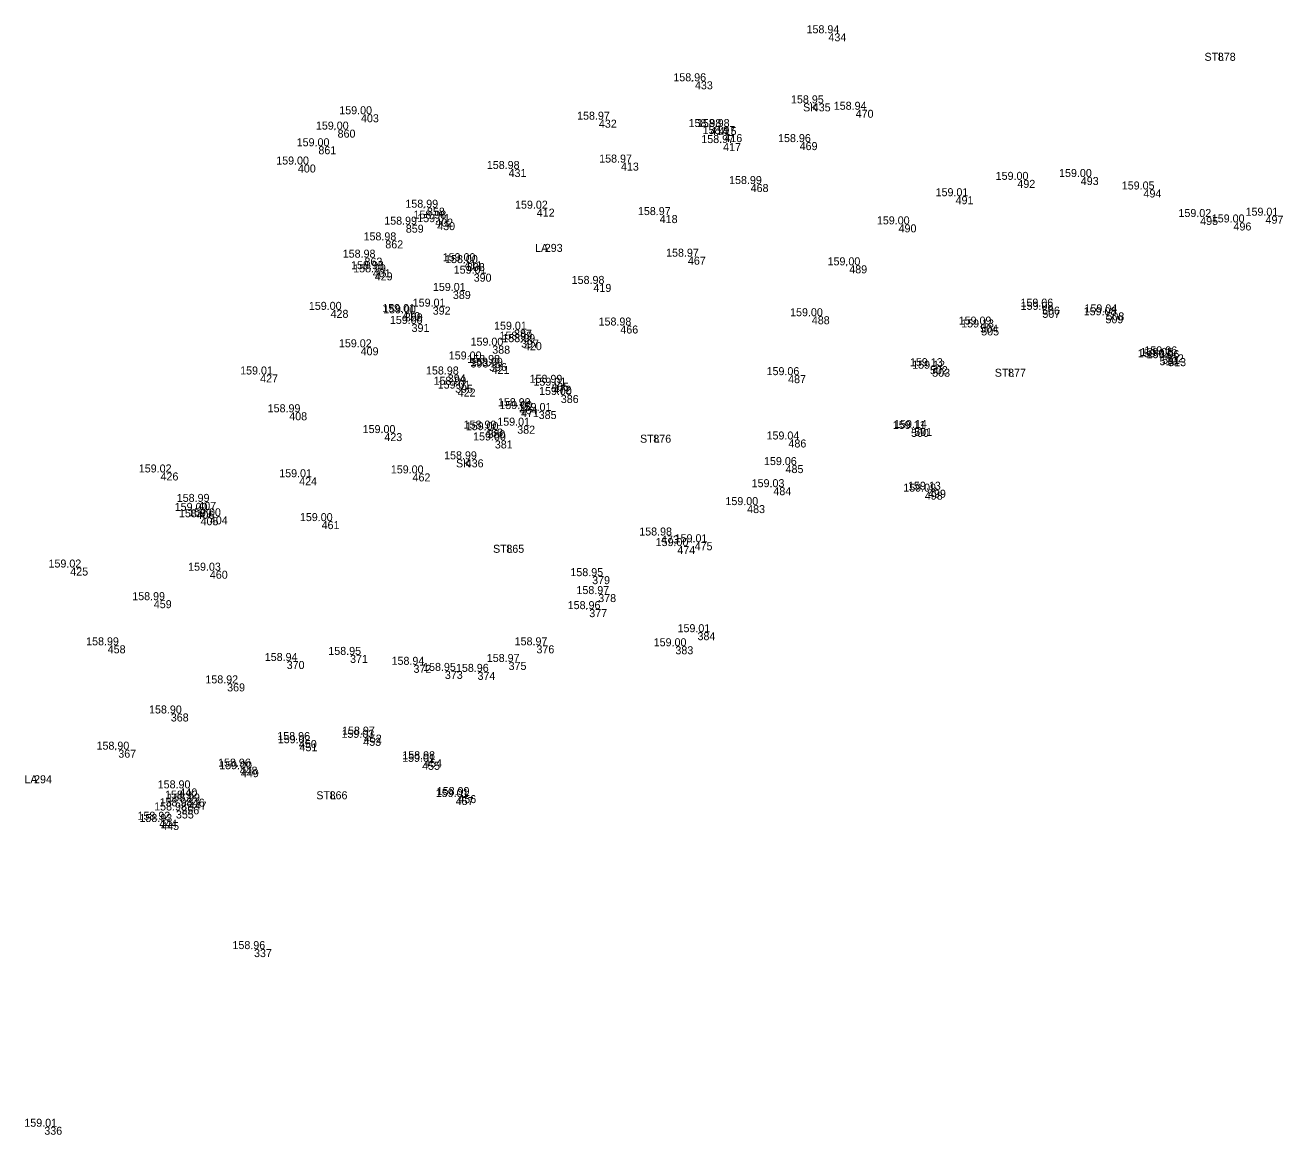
# Model space of a CAD drawing. Extents: x -583198 to -582878, y -1211024 to -1210637.
# Drawn here: x -583103.32 to -583064.04, y -1210915.85 to -1210881.19 of the extents above; entities that cross this region are included whole.
import ezdxf

# ---------------------------------------------------------------- set-up
doc = ezdxf.new("R2010")
doc.units = 0
for name, color, linetype in [('1   Kódy', 7, 'Continuous'), ('4   Body podrobné', 7, 'Continuous'), ('5   Body podrobné - čísla', 7, 'Continuous'), ('6   Body podrobné - výšky', 7, 'Continuous')]:
    doc.layers.add(name, color=color, linetype=linetype)

msp = doc.modelspace()

# ---------------------------------------------------------------- linework, layer by layer
at = {"layer": '4   Body podrobné'}
for p, q in [((-583078.32, -1210881.44), (-583078.319, -1210881.44)), ((-583066.16, -1210882.05), (-583066.159, -1210882.05)), ((-583082.49, -1210882.94), (-583082.489, -1210882.94)), ((-583078.81, -1210883.63), (-583078.809, -1210883.63)), ((-583077.47, -1210883.83), (-583077.469, -1210883.83)), ((-583092.92, -1210883.97), (-583092.919, -1210883.97)), ((-583085.49, -1210884.14), (-583085.489, -1210884.14)), ((-583093.65, -1210884.45), (-583093.649, -1210884.45)), ((-583082.01, -1210884.37), (-583082.009, -1210884.37)), ((-583081.75, -1210884.37), (-583081.749, -1210884.37)), ((-583081.57, -1210884.59), (-583081.569, -1210884.59)), ((-583094.25, -1210884.97), (-583094.249, -1210884.97)), ((-583081.61, -1210884.87), (-583081.609, -1210884.87)), ((-583079.22, -1210884.84), (-583079.219, -1210884.84)), ((-583084.8, -1210885.48), (-583084.799, -1210885.48)), ((-583094.89, -1210885.54), (-583094.889, -1210885.54)), ((-583088.31, -1210885.68), (-583088.309, -1210885.68)), ((-583080.75, -1210886.15), (-583080.749, -1210886.15)), ((-583072.42, -1210886.02), (-583072.419, -1210886.02)), ((-583070.44, -1210885.93), (-583070.439, -1210885.93)), ((-583068.48, -1210886.32), (-583068.479, -1210886.32)), ((-583074.35, -1210886.53), (-583074.349, -1210886.53)), ((-583090.86, -1210886.89), (-583090.859, -1210886.89)), ((-583087.43, -1210886.92), (-583087.429, -1210886.92)), ((-583091.52, -1210887.42), (-583091.519, -1210887.42)), ((-583090.6, -1210887.23), (-583090.599, -1210887.23)), ((-583090.54, -1210887.34), (-583090.539, -1210887.34)), ((-583083.59, -1210887.12), (-583083.589, -1210887.12)), ((-583076.13, -1210887.41), (-583076.129, -1210887.41)), ((-583066.71, -1210887.18), (-583066.709, -1210887.18)), ((-583065.67, -1210887.35), (-583065.669, -1210887.35)), ((-583064.67, -1210887.14), (-583064.669, -1210887.14)), ((-583092.16, -1210887.91), (-583092.159, -1210887.91)), ((-583087.18, -1210888.02), (-583087.179, -1210888.02)), ((-583092.81, -1210888.45), (-583092.809, -1210888.45)), ((-583089.69, -1210888.56), (-583089.689, -1210888.56)), ((-583089.61, -1210888.62), (-583089.609, -1210888.62)), ((-583082.71, -1210888.42), (-583082.709, -1210888.42)), ((-583092.55, -1210888.81), (-583092.549, -1210888.81)), ((-583092.49, -1210888.91), (-583092.489, -1210888.91)), ((-583089.4, -1210888.95), (-583089.399, -1210888.95)), ((-583077.67, -1210888.69), (-583077.669, -1210888.69)), ((-583085.66, -1210889.27), (-583085.659, -1210889.27)), ((-583090.05, -1210889.49), (-583090.049, -1210889.49)), ((-583093.87, -1210890.08), (-583093.869, -1210890.08)), ((-583091.63, -1210890.15), (-583091.629, -1210890.15)), ((-583091.55, -1210890.19), (-583091.549, -1210890.19)), ((-583090.68, -1210889.98), (-583090.679, -1210889.98)), ((-583071.65, -1210889.98), (-583071.649, -1210889.98)), ((-583071.64, -1210890.08), (-583071.639, -1210890.08)), ((-583069.64, -1210890.16), (-583069.639, -1210890.16)), ((-583091.34, -1210890.52), (-583091.339, -1210890.52)), ((-583084.82, -1210890.57), (-583084.819, -1210890.57)), ((-583078.84, -1210890.28), (-583078.839, -1210890.28)), ((-583073.58, -1210890.54), (-583073.579, -1210890.54)), ((-583073.55, -1210890.63), (-583073.549, -1210890.63)), ((-583069.67, -1210890.25), (-583069.669, -1210890.25)), ((-583088.14, -1210890.7), (-583088.139, -1210890.7)), ((-583087.92, -1210891.01), (-583087.919, -1210891.01)), ((-583092.93, -1210891.25), (-583092.929, -1210891.25)), ((-583088.82, -1210891.2), (-583088.819, -1210891.2)), ((-583087.83, -1210891.09), (-583087.829, -1210891.09)), ((-583089.5, -1210891.63), (-583089.499, -1210891.63)), ((-583088.92, -1210891.74), (-583088.919, -1210891.74)), ((-583067.98, -1210891.56), (-583067.979, -1210891.56)), ((-583067.9, -1210891.52), (-583067.899, -1210891.52)), ((-583067.78, -1210891.47), (-583067.779, -1210891.47)), ((-583067.71, -1210891.59), (-583067.709, -1210891.59)), ((-583096.07, -1210892.1), (-583096.069, -1210892.1)), ((-583090.21, -1210892.1), (-583090.209, -1210892.1)), ((-583088.84, -1210891.83), (-583088.839, -1210891.83)), ((-583079.58, -1210892.12), (-583079.579, -1210892.12)), ((-583075.15, -1210891.84), (-583075.149, -1210891.84)), ((-583075.08, -1210891.92), (-583075.079, -1210891.92)), ((-583072.71, -1210891.92), (-583072.709, -1210891.92)), ((-583089.98, -1210892.42), (-583089.979, -1210892.42)), ((-583089.9, -1210892.54), (-583089.899, -1210892.54)), ((-583086.98, -1210892.36), (-583086.979, -1210892.36)), ((-583086.91, -1210892.45), (-583086.909, -1210892.45)), ((-583086.68, -1210892.74), (-583086.679, -1210892.74)), ((-583095.16, -1210893.28), (-583095.159, -1210893.28)), ((-583087.97, -1210893.09), (-583087.969, -1210893.09)), ((-583087.92, -1210893.18), (-583087.919, -1210893.18)), ((-583087.37, -1210893.24), (-583087.369, -1210893.24)), ((-583088.04, -1210893.7), (-583088.039, -1210893.7)), ((-583075.64, -1210893.77), (-583075.639, -1210893.77)), ((-583092.19, -1210893.93), (-583092.189, -1210893.93)), ((-583089.04, -1210893.79), (-583089.039, -1210893.79)), ((-583088.97, -1210893.84), (-583088.969, -1210893.84)), ((-583088.74, -1210894.16), (-583088.739, -1210894.16)), ((-583083.79, -1210893.98), (-583083.789, -1210893.98)), ((-583079.57, -1210894.13), (-583079.569, -1210894.13)), ((-583075.74, -1210893.8), (-583075.739, -1210893.8)), ((-583089.65, -1210894.75), (-583089.649, -1210894.75)), ((-583079.66, -1210894.93), (-583079.659, -1210894.93)), ((-583099.18, -1210895.16), (-583099.179, -1210895.16)), ((-583094.85, -1210895.31), (-583094.849, -1210895.31)), ((-583091.31, -1210895.19), (-583091.309, -1210895.19)), ((-583080.04, -1210895.62), (-583080.039, -1210895.62)), ((-583075.21, -1210895.7), (-583075.209, -1210895.7)), ((-583098, -1210896.08), (-583097.999, -1210896.08)), ((-583075.31, -1210895.76), (-583075.309, -1210895.76)), ((-583098.06, -1210896.36), (-583098.059, -1210896.36)), ((-583097.64, -1210896.53), (-583097.639, -1210896.53)), ((-583080.86, -1210896.18), (-583080.859, -1210896.18)), ((-583097.93, -1210896.56), (-583097.929, -1210896.56)), ((-583094.15, -1210896.68), (-583094.149, -1210896.68)), ((-583083.55, -1210897.13), (-583083.549, -1210897.13)), ((-583088.38, -1210897.42), (-583088.379, -1210897.42)), ((-583083.04, -1210897.46), (-583083.039, -1210897.46)), ((-583082.5, -1210897.34), (-583082.499, -1210897.34)), ((-583102, -1210898.13), (-583101.999, -1210898.13)), ((-583097.64, -1210898.23), (-583097.639, -1210898.23)), ((-583085.7, -1210898.4), (-583085.699, -1210898.4)), ((-583099.39, -1210899.15), (-583099.389, -1210899.15)), ((-583085.51, -1210898.96), (-583085.509, -1210898.96)), ((-583085.79, -1210899.43), (-583085.789, -1210899.43)), ((-583082.41, -1210900.15), (-583082.409, -1210900.15)), ((-583100.83, -1210900.56), (-583100.829, -1210900.56)), ((-583087.44, -1210900.56), (-583087.439, -1210900.56)), ((-583083.1, -1210900.59), (-583083.099, -1210900.59)), ((-583095.24, -1210901.05), (-583095.239, -1210901.05)), ((-583093.26, -1210900.86), (-583093.259, -1210900.86)), ((-583091.28, -1210901.17), (-583091.279, -1210901.17)), ((-583088.31, -1210901.08), (-583088.309, -1210901.08)), ((-583090.3, -1210901.36), (-583090.299, -1210901.36)), ((-583089.28, -1210901.39), (-583089.279, -1210901.39)), ((-583097.1, -1210901.75), (-583097.099, -1210901.75)), ((-583098.86, -1210902.69), (-583098.859, -1210902.69)), ((-583094.86, -1210903.52), (-583094.859, -1210903.52)), ((-583092.85, -1210903.45), (-583092.849, -1210903.45)), ((-583092.83, -1210903.35), (-583092.829, -1210903.35)), ((-583100.5, -1210903.82), (-583100.499, -1210903.82)), ((-583094.84, -1210903.62), (-583094.839, -1210903.62)), ((-583096.71, -1210904.35), (-583096.709, -1210904.35)), ((-583091.01, -1210904.2), (-583091.009, -1210904.2)), ((-583090.95, -1210904.12), (-583090.949, -1210904.12)), ((-583103.13, -1210904.62), (-583103.129, -1210904.62)), ((-583096.67, -1210904.43), (-583096.669, -1210904.43)), ((-583098.59, -1210905.03), (-583098.589, -1210905.03)), ((-583093.9, -1210905.12), (-583093.899, -1210905.12)), ((-583098.36, -1210905.35), (-583098.359, -1210905.35)), ((-583098.3, -1210905.44), (-583098.299, -1210905.44)), ((-583089.96, -1210905.3), (-583089.959, -1210905.3)), ((-583089.88, -1210905.24), (-583089.879, -1210905.24)), ((-583098.7, -1210905.72), (-583098.699, -1210905.72)), ((-583098.53, -1210905.59), (-583098.529, -1210905.59)), ((-583099.22, -1210906.01), (-583099.219, -1210906.01)), ((-583099.16, -1210906.08), (-583099.159, -1210906.08)), ((-583096.26, -1210910.05), (-583096.259, -1210910.05)), ((-583102.81, -1210915.6), (-583102.809, -1210915.6))]:
    msp.add_line(p, q, dxfattribs=at)

# ---------------------------------------------------------------- texts
at = {"layer": '1   Kódy'}
for s, p in [('STL', (-583066.482, -1210882.3)), ('SK', (-583079.019, -1210883.88)), ('LA', (-583087.39, -1210888.27)), ('STL', (-583073.032, -1210892.17)), ('STL', (-583084.112, -1210894.23)), ('SK', (-583089.859, -1210895)), ('STL', (-583088.702, -1210897.67)), ('LA', (-583103.34, -1210904.87)), ('STL', (-583094.222, -1210905.37))]:
    msp.add_text(s, height=0.25, dxfattribs=at).set_placement(p)
at = {"layer": '5   Body podrobné - čísla'}
for s, p in [(' 434', (-583078.32, -1210881.69)), (' 878', (-583066.16, -1210882.3)), (' 433', (-583082.49, -1210883.19)), (' 435', (-583078.81, -1210883.88)), (' 470', (-583077.47, -1210884.08)), (' 403', (-583092.92, -1210884.22)), (' 432', (-583085.49, -1210884.39)), (' 860', (-583093.65, -1210884.7)), (' 414', (-583082.01, -1210884.62)), (' 415', (-583081.75, -1210884.62)), (' 416', (-583081.57, -1210884.84)), (' 861', (-583094.25, -1210885.22)), (' 417', (-583081.61, -1210885.12)), (' 469', (-583079.22, -1210885.09)), (' 413', (-583084.8, -1210885.73)), (' 400', (-583094.89, -1210885.79)), (' 431', (-583088.31, -1210885.93)), (' 493', (-583070.44, -1210886.18)), (' 468', (-583080.75, -1210886.4)), (' 492', (-583072.42, -1210886.27)), (' 494', (-583068.48, -1210886.57)), (' 491', (-583074.35, -1210886.78)), (' 858', (-583090.86, -1210887.14)), (' 412', (-583087.43, -1210887.17)), (' 859', (-583091.52, -1210887.67)), (' 402', (-583090.6, -1210887.48)), (' 430', (-583090.54, -1210887.59)), (' 418', (-583083.59, -1210887.37)), (' 490', (-583076.13, -1210887.66)), (' 495', (-583066.71, -1210887.43)), (' 496', (-583065.67, -1210887.6)), (' 497', (-583064.67, -1210887.39)), (' 862', (-583092.16, -1210888.16)), (' 293', (-583087.18, -1210888.27)), (' 863', (-583092.81, -1210888.7)), (' 411', (-583089.69, -1210888.81)), (' 398', (-583089.61, -1210888.87)), (' 467', (-583082.71, -1210888.67)), (' 401', (-583092.55, -1210889.06)), (' 429', (-583092.49, -1210889.16)), (' 390', (-583089.4, -1210889.2)), (' 489', (-583077.67, -1210888.94)), (' 419', (-583085.66, -1210889.52)), (' 389', (-583090.05, -1210889.74)), (' 428', (-583093.87, -1210890.33)), (' 410', (-583091.63, -1210890.4)), (' 399', (-583091.55, -1210890.44)), (' 392', (-583090.68, -1210890.23)), (' 506', (-583071.65, -1210890.23)), (' 507', (-583071.64, -1210890.33)), (' 509', (-583069.67, -1210890.5)), (' 508', (-583069.64, -1210890.41)), (' 391', (-583091.34, -1210890.77)), (' 466', (-583084.82, -1210890.82)), (' 488', (-583078.84, -1210890.53)), (' 504', (-583073.58, -1210890.79)), (' 505', (-583073.55, -1210890.88)), (' 387', (-583088.14, -1210890.95)), (' 397', (-583087.92, -1210891.26)), (' 409', (-583092.93, -1210891.5)), (' 388', (-583088.82, -1210891.45)), (' 420', (-583087.83, -1210891.34)), (' 393', (-583089.5, -1210891.88)), (' 396', (-583088.92, -1210891.99)), (' 510', (-583067.98, -1210891.81)), (' 511', (-583067.9, -1210891.77)), (' 512', (-583067.78, -1210891.72)), (' 513', (-583067.71, -1210891.84)), (' 427', (-583096.07, -1210892.35)), (' 394', (-583090.21, -1210892.35)), (' 421', (-583088.84, -1210892.08)), (' 487', (-583079.58, -1210892.37)), (' 502', (-583075.15, -1210892.09)), (' 503', (-583075.08, -1210892.17)), (' 877', (-583072.71, -1210892.17)), (' 395', (-583089.98, -1210892.67)), (' 422', (-583089.9, -1210892.79)), (' 465', (-583086.98, -1210892.61)), (' 472', (-583086.91, -1210892.7)), (' 386', (-583086.68, -1210892.99)), (' 408', (-583095.16, -1210893.53)), (' 464', (-583087.97, -1210893.34)), (' 471', (-583087.92, -1210893.43)), (' 385', (-583087.37, -1210893.49)), (' 382', (-583088.04, -1210893.95)), (' 501', (-583075.64, -1210894.02)), (' 423', (-583092.19, -1210894.18)), (' 463', (-583089.04, -1210894.04)), (' 380', (-583088.97, -1210894.09)), (' 381', (-583088.74, -1210894.41)), (' 876', (-583083.79, -1210894.23)), (' 486', (-583079.57, -1210894.38)), (' 500', (-583075.74, -1210894.05)), (' 436', (-583089.65, -1210895)), (' 485', (-583079.66, -1210895.18)), (' 426', (-583099.18, -1210895.41)), (' 424', (-583094.85, -1210895.56)), (' 462', (-583091.31, -1210895.44)), (' 484', (-583080.04, -1210895.87)), (' 499', (-583075.21, -1210895.95)), (' 407', (-583098, -1210896.33)), (' 498', (-583075.31, -1210896.01)), (' 406', (-583098.06, -1210896.61)), (' 404', (-583097.64, -1210896.78)), (' 483', (-583080.86, -1210896.43)), (' 405', (-583097.93, -1210896.81)), (' 461', (-583094.15, -1210896.93)), (' 473', (-583083.55, -1210897.38)), (' 865', (-583088.38, -1210897.67)), (' 474', (-583083.04, -1210897.71)), (' 475', (-583082.5, -1210897.59)), (' 425', (-583102, -1210898.38)), (' 460', (-583097.64, -1210898.48)), (' 379', (-583085.7, -1210898.65)), (' 459', (-583099.39, -1210899.4)), (' 378', (-583085.51, -1210899.21)), (' 377', (-583085.79, -1210899.68)), (' 384', (-583082.41, -1210900.4)), (' 458', (-583100.83, -1210900.81)), (' 376', (-583087.44, -1210900.81)), (' 383', (-583083.1, -1210900.84)), (' 370', (-583095.24, -1210901.3)), (' 371', (-583093.26, -1210901.11)), (' 372', (-583091.28, -1210901.42)), (' 375', (-583088.31, -1210901.33)), (' 373', (-583090.3, -1210901.61)), (' 374', (-583089.28, -1210901.64)), (' 369', (-583097.1, -1210902)), (' 368', (-583098.86, -1210902.94)), (' 450', (-583094.86, -1210903.77)), (' 453', (-583092.85, -1210903.7)), (' 452', (-583092.83, -1210903.6)), (' 367', (-583100.5, -1210904.07)), (' 451', (-583094.84, -1210903.87)), (' 448', (-583096.71, -1210904.6)), (' 455', (-583091.01, -1210904.45)), (' 454', (-583090.95, -1210904.37)), (' 294', (-583103.13, -1210904.87)), (' 449', (-583096.67, -1210904.68)), (' 440', (-583098.59, -1210905.28)), (' 866', (-583093.9, -1210905.37)), (' 446', (-583098.36, -1210905.6)), (' 447', (-583098.3, -1210905.69)), (' 457', (-583089.96, -1210905.55)), (' 456', (-583089.88, -1210905.49)), (' 355', (-583098.7, -1210905.97)), (' 356', (-583098.53, -1210905.84)), (' 444', (-583099.22, -1210906.26)), (' 445', (-583099.16, -1210906.33)), (' 337', (-583096.26, -1210910.3)), (' 336', (-583102.81, -1210915.85))]:
    msp.add_text(s, height=0.25, dxfattribs=at).set_placement(p)
at = {"layer": '6   Body podrobné - výšky'}
for s, p in [('158.94', (-583078.912, -1210881.44)), ('158.96', (-583083.071, -1210882.94)), ('158.95', (-583079.397, -1210883.63)), ('159.00', (-583093.505, -1210883.97)), ('158.97', (-583086.078, -1210884.14)), ('158.94', (-583078.062, -1210883.83)), ('159.00', (-583094.235, -1210884.45)), ('158.98', (-583082.597, -1210884.37)), ('158.98', (-583082.337, -1210884.37)), ('158.97', (-583082.158, -1210884.59)), ('159.00', (-583094.835, -1210884.97)), ('158.97', (-583082.198, -1210884.87)), ('158.96', (-583079.801, -1210884.84)), ('159.00', (-583095.475, -1210885.54)), ('158.98', (-583088.897, -1210885.68)), ('158.97', (-583085.388, -1210885.48)), ('158.99', (-583081.331, -1210886.15)), ('159.00', (-583073.005, -1210886.02)), ('159.00', (-583071.025, -1210885.93)), ('159.01', (-583074.881, -1210886.53)), ('159.05', (-583069.066, -1210886.32)), ('158.99', (-583091.441, -1210886.89)), ('159.02', (-583088.016, -1210886.92)), ('158.98', (-583091.187, -1210887.23)), ('159.01', (-583091.071, -1210887.34)), ('158.97', (-583084.178, -1210887.12)), ('159.02', (-583067.296, -1210887.18)), ('159.00', (-583066.255, -1210887.35)), ('159.01', (-583065.201, -1210887.14)), ('158.99', (-583092.101, -1210887.42)), ('159.00', (-583076.715, -1210887.41)), ('158.98', (-583092.747, -1210887.91)), ('158.98', (-583093.397, -1210888.45)), ('158.97', (-583083.298, -1210888.42)), ('158.98', (-583093.137, -1210888.81)), ('158.99', (-583093.071, -1210888.91)), ('159.00', (-583090.275, -1210888.56)), ('158.00', (-583090.2, -1210888.62)), ('159.00', (-583078.255, -1210888.69)), ('159.01', (-583089.931, -1210888.95)), ('158.98', (-583086.247, -1210889.27)), ('159.01', (-583090.581, -1210889.49)), ('159.00', (-583094.455, -1210890.08)), ('159.01', (-583091.211, -1210889.98)), ('159.06', (-583072.23, -1210889.98)), ('159.08', (-583072.226, -1210890.08)), ('159.01', (-583092.161, -1210890.15)), ('159.00', (-583092.135, -1210890.19)), ('159.00', (-583079.425, -1210890.28)), ('159.08', (-583070.256, -1210890.25)), ('159.04', (-583070.231, -1210890.16)), ('159.00', (-583091.925, -1210890.52)), ('159.01', (-583088.671, -1210890.7)), ('158.98', (-583085.407, -1210890.57)), ('159.09', (-583074.16, -1210890.54)), ('159.13', (-583074.082, -1210890.63)), ('159.02', (-583093.516, -1210891.25)), ('159.00', (-583089.405, -1210891.2)), ('158.99', (-583088.501, -1210891.01)), ('158.99', (-583088.411, -1210891.09)), ('159.00', (-583090.085, -1210891.63)), ('159.07', (-583068.567, -1210891.56)), ('159.05', (-583068.486, -1210891.52)), ('159.06', (-583068.36, -1210891.47)), ('159.06', (-583068.29, -1210891.59)), ('158.98', (-583089.507, -1210891.74)), ('158.99', (-583089.421, -1210891.83)), ('159.13', (-583075.682, -1210891.84)), ('159.12', (-583075.612, -1210891.92)), ('159.01', (-583096.601, -1210892.1)), ('158.98', (-583090.797, -1210892.1)), ('158.99', (-583090.561, -1210892.42)), ('158.99', (-583087.561, -1210892.36)), ('159.01', (-583087.441, -1210892.45)), ('159.06', (-583080.16, -1210892.12)), ('159.01', (-583090.431, -1210892.54)), ('159.00', (-583087.265, -1210892.74)), ('158.99', (-583088.551, -1210893.09)), ('159.00', (-583088.505, -1210893.18)), ('159.01', (-583087.901, -1210893.24)), ('158.99', (-583095.741, -1210893.28)), ('159.00', (-583092.775, -1210893.93)), ('158.99', (-583089.621, -1210893.79)), ('159.00', (-583089.555, -1210893.84)), ('159.01', (-583088.571, -1210893.7)), ('159.11', (-583076.218, -1210893.8)), ('159.14', (-583076.178, -1210893.77)), ('159.00', (-583089.325, -1210894.16)), ('159.04', (-583080.161, -1210894.13)), ('158.99', (-583090.231, -1210894.75)), ('159.02', (-583099.766, -1210895.16)), ('159.00', (-583091.895, -1210895.19)), ('159.06', (-583080.24, -1210894.93)), ('159.01', (-583095.381, -1210895.31)), ('159.03', (-583080.626, -1210895.62)), ('159.09', (-583075.89, -1210895.76)), ('159.13', (-583075.742, -1210895.7)), ('159.00', (-583098.645, -1210896.36)), ('158.99', (-583098.581, -1210896.08)), ('159.00', (-583081.445, -1210896.18)), ('158.99', (-583098.511, -1210896.56)), ('159.00', (-583098.225, -1210896.53)), ('159.00', (-583094.735, -1210896.68)), ('158.98', (-583084.137, -1210897.13)), ('159.00', (-583083.625, -1210897.46)), ('159.01', (-583083.031, -1210897.34)), ('159.02', (-583102.586, -1210898.13)), ('159.03', (-583098.226, -1210898.23)), ('158.95', (-583086.287, -1210898.4)), ('158.97', (-583086.098, -1210898.96)), ('158.99', (-583099.971, -1210899.15)), ('158.96', (-583086.371, -1210899.43)), ('159.01', (-583082.941, -1210900.15)), ('158.99', (-583101.411, -1210900.56)), ('158.97', (-583088.028, -1210900.56)), ('159.00', (-583083.685, -1210900.59)), ('158.94', (-583095.832, -1210901.05)), ('158.95', (-583093.847, -1210900.86)), ('158.97', (-583088.898, -1210901.08)), ('158.94', (-583091.872, -1210901.17)), ('158.95', (-583090.887, -1210901.36)), ('158.96', (-583089.861, -1210901.39)), ('158.92', (-583097.687, -1210901.75)), ('158.90', (-583099.446, -1210902.69)), ('159.03', (-583093.436, -1210903.45)), ('158.97', (-583093.418, -1210903.35)), ('158.90', (-583101.086, -1210903.82)), ('158.96', (-583095.441, -1210903.52)), ('159.02', (-583095.426, -1210903.62)), ('159.01', (-583091.541, -1210904.2)), ('158.98', (-583091.537, -1210904.12)), ('158.96', (-583097.291, -1210904.35)), ('159.00', (-583097.255, -1210904.43)), ('158.90', (-583099.176, -1210905.03)), ('158.92', (-583098.947, -1210905.35)), ('159.01', (-583090.491, -1210905.3)), ('158.99', (-583090.461, -1210905.24)), ('158.98', (-583099.287, -1210905.72)), ('158.98', (-583099.117, -1210905.59)), ('158.99', (-583098.881, -1210905.44)), ('158.92', (-583099.807, -1210906.01)), ('158.93', (-583099.747, -1210906.08)), ('158.96', (-583096.841, -1210910.05)), ('159.01', (-583103.341, -1210915.6))]:
    msp.add_text(s, height=0.25, dxfattribs=at).set_placement(p)

doc.saveas('drawing.dxf')
